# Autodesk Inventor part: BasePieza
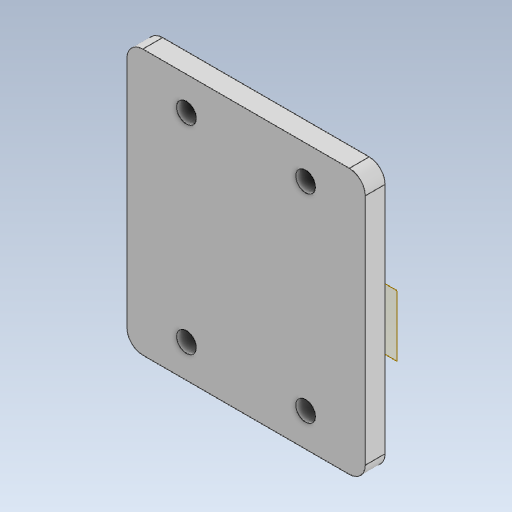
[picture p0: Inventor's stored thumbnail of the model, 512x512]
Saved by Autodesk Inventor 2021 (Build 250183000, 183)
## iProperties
Created: 2021-02
Part Number: BasePieza
Material: Genérico
Document SubType Name: Modeling
Designer: ATOUZA
Density: 1 g/cm^3
Appearance: Valor por defecto
Author: ATOUZA
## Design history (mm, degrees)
node "Plano de trabajo1"
sketch "Boceto1"
  geometry: L1 (0, -26.365)-(0, -13.632) reference; L2 (0, -13.632)-(-60, -13.632) reference; L3 (-60, -26.365)-(-60, -13.632) reference; L4 (0, -26.365)-(-60, -26.365) reference; L5 (0, 27.632)-(0, 40.365) reference; L6 (0, 40.365)-(-60, 40.365) reference; L7 (-60, 27.632)-(-60, 40.365) reference; L8 (0, 27.632)-(-60, 27.632) reference; L9 (-60, -26.365)-(0, -26.365); L10 (0, -26.365)-(0, 40.365); L11 (0, 40.365)-(-60, 40.365); L12 (-60, 40.365)-(-60, -26.365); L13 (-60, 7)-(0, 7); L14 (-30, 40.365)-(-30, -26.365); C1 r 2.5 at (-45, -18) reference; C2 r 2.5 at (-15, -18) reference; C3 r 2.5 at (-45, 32) reference; C4 r 2.5 at (-15, 32) reference; C5 r 2.5 at (-45, -18); C6 r 2.5 at (-15, -18); C7 r 2.5 at (-45, 32); C8 r 2.5 at (-15, 32); 1 further point
  constraints: 12 end point, 4 centre point, 4 coincident, 4 concentric, 4 midpoint, 2 parallel, 1 horizontal, 1 perpendicular
extrude "Extrusión1" new body sketch "Boceto1" distance "d0" = 5; taper "d1" = 0 deg
fillet "Empalme1" dims "d2" = 4
node "Sólido1"
node "Referencia1"
node "Referencia2"
